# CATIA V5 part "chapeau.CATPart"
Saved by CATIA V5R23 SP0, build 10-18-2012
Part number: chapeau
Definition: chapeau
Source: made
Bounding box of the stored display mesh (mm): x -80 to 80, y -84 to 84, z 0 to 22
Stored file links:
  C:\wamp\www\COURS\CONCEPTION GMP1\TITRE 01-CATIA VOLUMIQUE\05--ACTIONNEUR DE VANNE\prof\CORRECTION\Assemblage\chapeau.CATPart
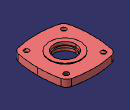
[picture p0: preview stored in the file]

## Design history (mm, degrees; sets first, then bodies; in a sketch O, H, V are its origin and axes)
Body1 "NONE" (main body)
  Solid1 "Manifold Solid #3701": solid without history
  Sketch1 "Esquisse.1" on face of Solid1, origin (0, 0, 20), H (1, 0, 0), V (0, 1, 0)
    projected arc E1 centre (53.9934, 57.6856) radius 4.2 from (49.7934, 57.6856) to (58.1934, 57.6856) ccw from edge [face of Solid1 | face of Solid1]
    projected arc E2 centre (53.9934, 57.6856) radius 4.2 from (58.1934, 57.6856) to (49.7934, 57.6856) ccw from edge [face of Solid1 | face of Solid1]
    projected arc E3 centre (-53.9934, 57.6856) radius 4.2 from (-58.1934, 57.6856) to (-49.7934, 57.6856) ccw from edge [face of Solid1 | face of Solid1]
    projected arc E4 centre (-53.9934, 57.6856) radius 4.2 from (-49.7934, 57.6856) to (-58.1934, 57.6856) ccw from edge [face of Solid1 | face of Solid1]
    projected arc E5 centre (-53.9934, -57.6856) radius 4.2 from (-58.1934, -57.6856) to (-49.7934, -57.6856) ccw from edge [face of Solid1 | face of Solid1]
    projected arc E6 centre (-53.9934, -57.6856) radius 4.2 from (-49.7934, -57.6856) to (-58.1934, -57.6856) ccw from edge [face of Solid1 | face of Solid1]
    projected arc E7 centre (53.9934, -57.6856) radius 4.2 from (49.7934, -57.6856) to (58.1934, -57.6856) ccw from edge [face of Solid1 | face of Solid1]
    projected arc E8 centre (53.9934, -57.6856) radius 4.2 from (58.1934, -57.6856) to (49.7934, -57.6856) ccw from edge [face of Solid1 | face of Solid1]
  Pad1 "Extrusion.1": profile Sketch1, direction (0, 0, 1), up to face of Solid1
  Sketch2 "Esquisse.2" on face of Solid1, origin (56.2847, 50.5018, 20), H (1, 0, 0), V (0, 1, 0)
    point P1 (-2.2914, 7.1837)
    reference projected arc E1 centre (-2.2914, 7.1837) radius 20 from (17.2796, 11.3041) to (2.3235, 26.644) ccw from edge [face of Solid1 | face of Solid1]
    concentricity: P1 E1
  Hole1 "Trou.1": placed by Sketch2, at (53.9934, 57.6856, 20) direction (0, 0, -1), diameter 8.4, up to face of Solid1, counterbore diameter 14, counterbore depth 8
  Sketch3 "Esquisse.3" on face of Solid1, origin (0, 0, 20), H (1, 0, 0), V (0, 1, 0)
    point P1 (53.9934, -57.6856)
    point P2 (-53.9934, -57.6856)
    point P3 (-53.9934, 57.6856)
    reference projected arc E1 centre (53.9934, -57.6856) radius 20 from (58.6082, -77.1459) to (73.5643, -61.806) ccw from edge [face of Solid1 | face of Solid1]
    reference projected arc E2 centre (-53.9934, -57.6856) radius 20 from (-73.5643, -61.806) to (-58.6082, -77.1459) ccw from edge [face of Solid1 | face of Solid1]
    reference projected arc E3 centre (-53.9934, 57.6856) radius 20 from (-58.6082, 77.1459) to (-73.5643, 61.806) ccw from edge [face of Solid1 | face of Solid1]
    concentricity: P1 E1, E2 P2, P3 E3
  UserPattern1 "Répétition personnalisée.1": of Hole1, copies 4, at the points of Sketch3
